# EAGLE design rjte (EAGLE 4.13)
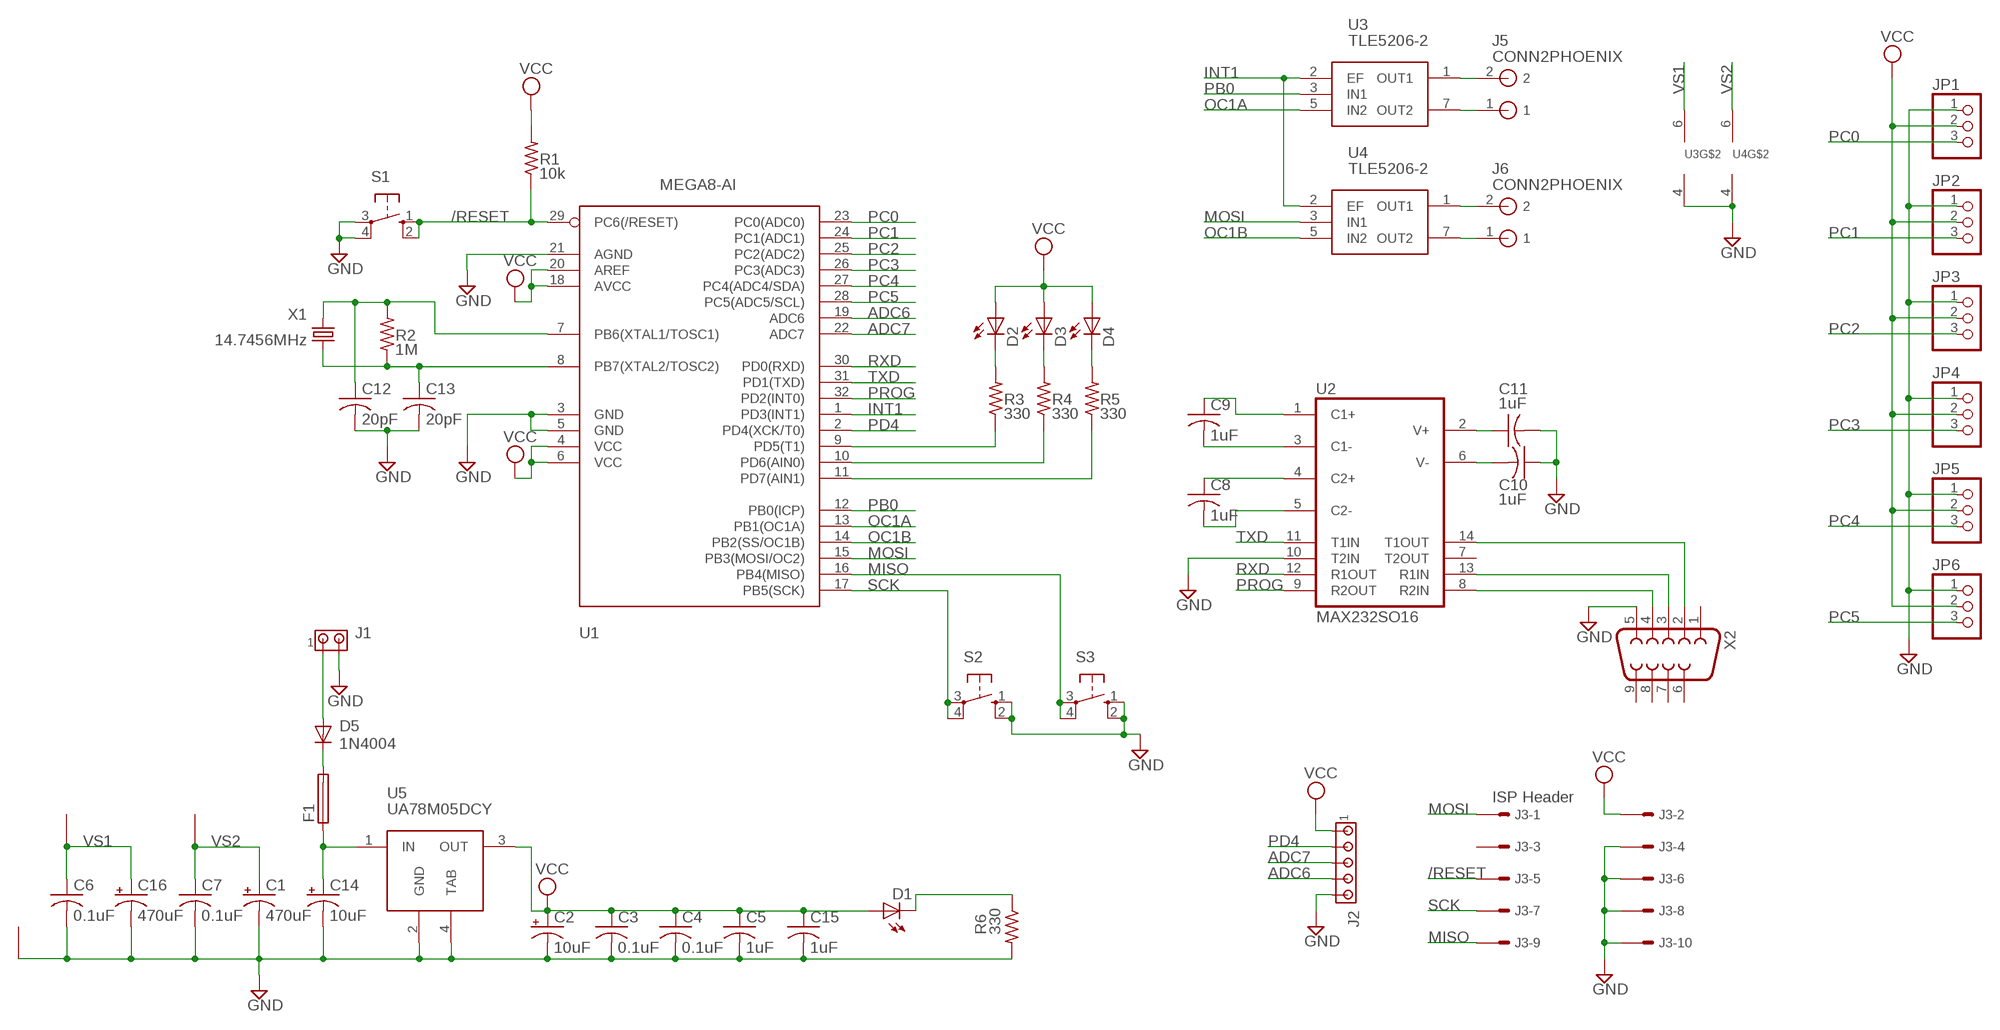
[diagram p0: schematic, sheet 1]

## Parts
C1  470uF  CPOL-USE5-10.5  [E5-10,5]
C2  10uF  CPOL-USB45181A  [B45181A]
C3  0.1uF  C-US025-030X050  [C025-030X050]
C4  0.1uF  C-US025-030X050  [C025-030X050]
C5  1uF  C-US025-025X050  [C025-025X050]
C6  0.1uF  C-US025-030X050  [C025-030X050]
C7  0.1uF  C-US025-030X050  [C025-030X050]
C8  1uF  C-US025-025X050  [C025-025X050]
C9  1uF  C-US025-025X050  [C025-025X050]
C10  1uF  C-US025-025X050  [C025-025X050]
C11  1uF  C-US025-025X050  [C025-025X050]
C12  20pF  C-US025-025X050  [C025-025X050]
C13  20pF  C-US025-025X050  [C025-025X050]
C14  10uF  CPOL-USB45181A  [B45181A]
C15  1uF  C-US025-025X050  [C025-025X050]
C16  470uF  CPOL-USE5-10.5  [E5-10,5]
D1  LED3MM  [LED3MM]
D2  LED3MM  [LED3MM]
D3  LED3MM  [LED3MM]
D4  LED3MM  [LED3MM]
D5  1N4004  [DO41-10]
F1  PICOFUSE  [PICOFUSE]
J1  MTA02-100  [10X02MTA]
J2  MTA05-100  [10X05MTA]
J3  ISP Header  057-010-1  [057-010-1]
J5  CONN2PHOENIX  [TB2]
J6  CONN2PHOENIX  [TB2]
JP1  PINHD-1X3  [1X03]
JP2  PINHD-1X3  [1X03]
JP3  PINHD-1X3  [1X03]
JP4  PINHD-1X3  [1X03]
JP5  PINHD-1X3  [1X03]
JP6  PINHD-1X3  [1X03]
R1  10k  R-US_0204/7  [0204/7]
R2  1M  R-US_0207/10  [0207/10]
R3  330  R-US_0207/10  [0207/10]
R4  330  R-US_0207/10  [0207/10]
R5  330  R-US_0207/10  [0207/10]
R6  330  R-US_0207/10  [0207/10]
S1  10-XX  [B3F-10XX]
S2  10-XX  [B3F-10XX]
S3  10-XX  [B3F-10XX]
U1  MEGA8-AI  [TQFP32-08]
U2  MAX232SO16  [SO16]
U3  TLE5206-2  TLE5206-2TLE5206-2  [TO220-7-11]
U4  TLE5206-2  TLE5206-2TLE5206-2  [TO220-7-11]
U5  UA78M05DCY  [SOT223]
U$1  12AWG_PAD  [12AWG_PAD]
U$3  12AWG_PAD  [12AWG_PAD]
U$4  12AWG_PAD  [12AWG_PAD]
X1  14.7456MHz  CRYTALHC49U-V  [HC49U-V]
X2  F09H  [F09H]

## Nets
/RESET: J3.5 R1.1 S1.1(S) S1.2(S1) U1.29(PC6(/RESET))
ADC6: J2.4 U1.19(ADC6)
ADC7: J2.3 U1.22(ADC7)
GND: C1.- C2.- C3.2 C4.2 C5.2 C6.2 C7.2 C10.1 C11.2 C12.2 C13.2 C14.- C15.2 C16.- J1.2 J2.5 J3.4 J3.6 J3.8 J3.10 JP1.1 JP2.1 JP3.1 JP4.1 JP5.1 JP6.1 R6.2 S1.3(P) S1.4(P1) S2.1(S) S2.2(S1) S3.1(S) S3.2(S1) U1.3(GND) U1.5(GND) U1.21(AGND) U2.10(T2IN) U3.4(GND) U4.4(GND) U5.2(GND) U5.4(TAB) U$4.P$1 X2.5
INT1: U1.1(PD3(INT1)) U3.2(EF) U4.2(EF)
MISO: J3.9 S3.3(P) S3.4(P1) U1.16(PB4(MISO))
MOSI: J3.1 U1.15(PB3(MOSI/OC2)) U4.3(IN1)
N$1: C13.1 R2.1 U1.8(PB7(XTAL2/TOSC2)) X1.1
N$2: C12.1 R2.2 U1.7(PB6(XTAL1/TOSC1)) X1.2
N$3: C8.1 U2.4(C2+)
N$4: C8.2 U2.5(C2-)
N$5: C9.2 U2.3(C1-)
N$6: C9.1 U2.1(C1+)
N$7: C10.2 U2.6(V-)
N$8: C11.1 U2.2(V+)
N$9: U2.14(T1OUT) X2.2
N$10: U2.13(R1IN) X2.3
N$11: U2.8(R2IN) X2.4
N$12: J5.2 U3.1(OUT1)
N$13: D2.K(C) R3.2
N$14: D3.K(C) R4.2
N$15: D4.K(C) R5.2
N$16: R5.1 U1.11(PD7(AIN1))
N$17: R4.1 U1.10(PD6(AIN0))
N$18: D1.K(C) R6.1
N$19: R3.1 U1.9(PD5(T1))
N$20: J5.1 U3.7(OUT2)
N$21: J6.2 U4.1(OUT1)
N$22: J6.1 U4.7(OUT2)
N$23: C14.+ F1.1 U5.1(IN)
N$24: D5.C F1.2
N$25: D5.A J1.1
OC1A: U1.13(PB1(OC1A)) U3.5(IN2)
OC1B: U1.14(PB2(SS/OC1B)) U4.5(IN2)
PB0: U1.12(PB0(ICP)) U3.3(IN1)
PC0: JP1.3 U1.23(PC0(ADC0))
PC1: JP2.3 U1.24(PC1(ADC1))
PC2: JP3.3 U1.25(PC2(ADC2))
PC3: JP4.3 U1.26(PC3(ADC3))
PC4: JP5.3 U1.27(PC4(ADC4/SDA))
PC5: JP6.3 U1.28(PC5(ADC5/SCL))
PD4: J2.2 U1.2(PD4(XCK/T0))
PROG: U1.32(PD2(INT0)) U2.9(R2OUT)
RXD: U1.30(PD0(RXD)) U2.12(R1OUT)
SCK: J3.7 S2.3(P) S2.4(P1) U1.17(PB5(SCK))
TXD: U1.31(PD1(TXD)) U2.11(T1IN)
VCC: C2.+ C3.1 C4.1 C5.1 C15.1 D1.A D2.A D3.A D4.A J2.1 J3.2 JP1.2 JP2.2 JP3.2 JP4.2 JP5.2 JP6.2 R1.2 U1.4(VCC) U1.6(VCC) U1.18(AVCC) U1.20(AREF) U5.3(OUT)
VS1: C6.1 C16.+ U3.6(VS) U$1.P$1
VS2: C1.+ C7.1 U4.6(VS) U$3.P$1
Unconnected: J3.3 U2.7(T2OUT) X2.1 X2.6 X2.7 X2.8 X2.9

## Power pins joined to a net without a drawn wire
GND: U2.15(GND)
VCC: U2.16(VCC)

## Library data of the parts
C1 C2 C14 C16 = rcl:CPOL-US: POLARIZED CAPACITOR, American symbol
C3-C13 C15 = rcl:C-US: CAPACITOR, American symbol
D1-D4 = led:LED: LED
D5 = diode:1N4004: DIODE
F1 = fuse:PICOFUSE: PICOFUSE
J1 = con-amp:MTA02-100: AMP connector
J2 = con-amp:MTA05-100: AMP connector
J3 = con-panduit:057-010-: CONNECTOR 10-pin series 057 contact pc board low profile headers
J5 J6 = rjte:CONN2
JP1-JP6 = rjte:PINHD-1X3: PIN HEADER
R1-R6 = rcl:R-US_: RESISTOR, American symbol
S1-S3 = switch-omron:10-XX: OMRON SWITCH
U1 = atmel:MEGA8: MICROCONTROLLER 8 Kbytes FLASH 1 kbytes SRAM 512 bytes EEPROM USART 6-channel 10 bit ADC 2-channel 8 bit ADC
U2 = rjte:MAX232: RS232 TRANSEIVER
U3 U4 = rjte:TLE5206-2
U5 = rjte:UA78M05
U$1 U$3 U$4 = rjte:12AWG_PAD
X1 = crystal:CRYTAL: CRYSTAL
X2 = rjte:F09: SUB-D

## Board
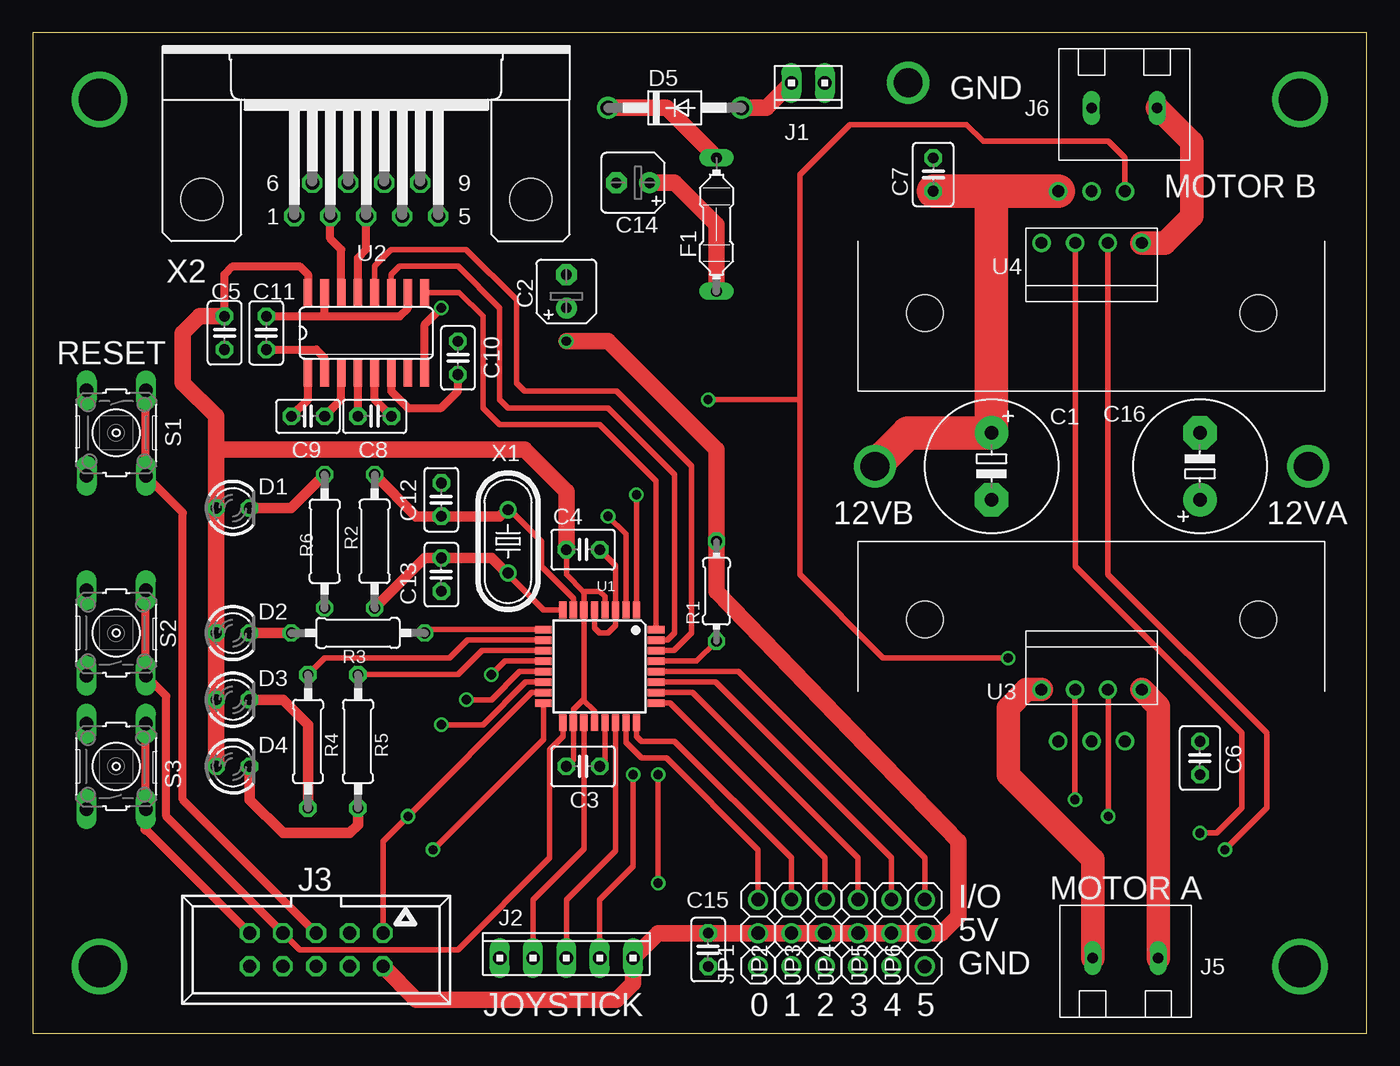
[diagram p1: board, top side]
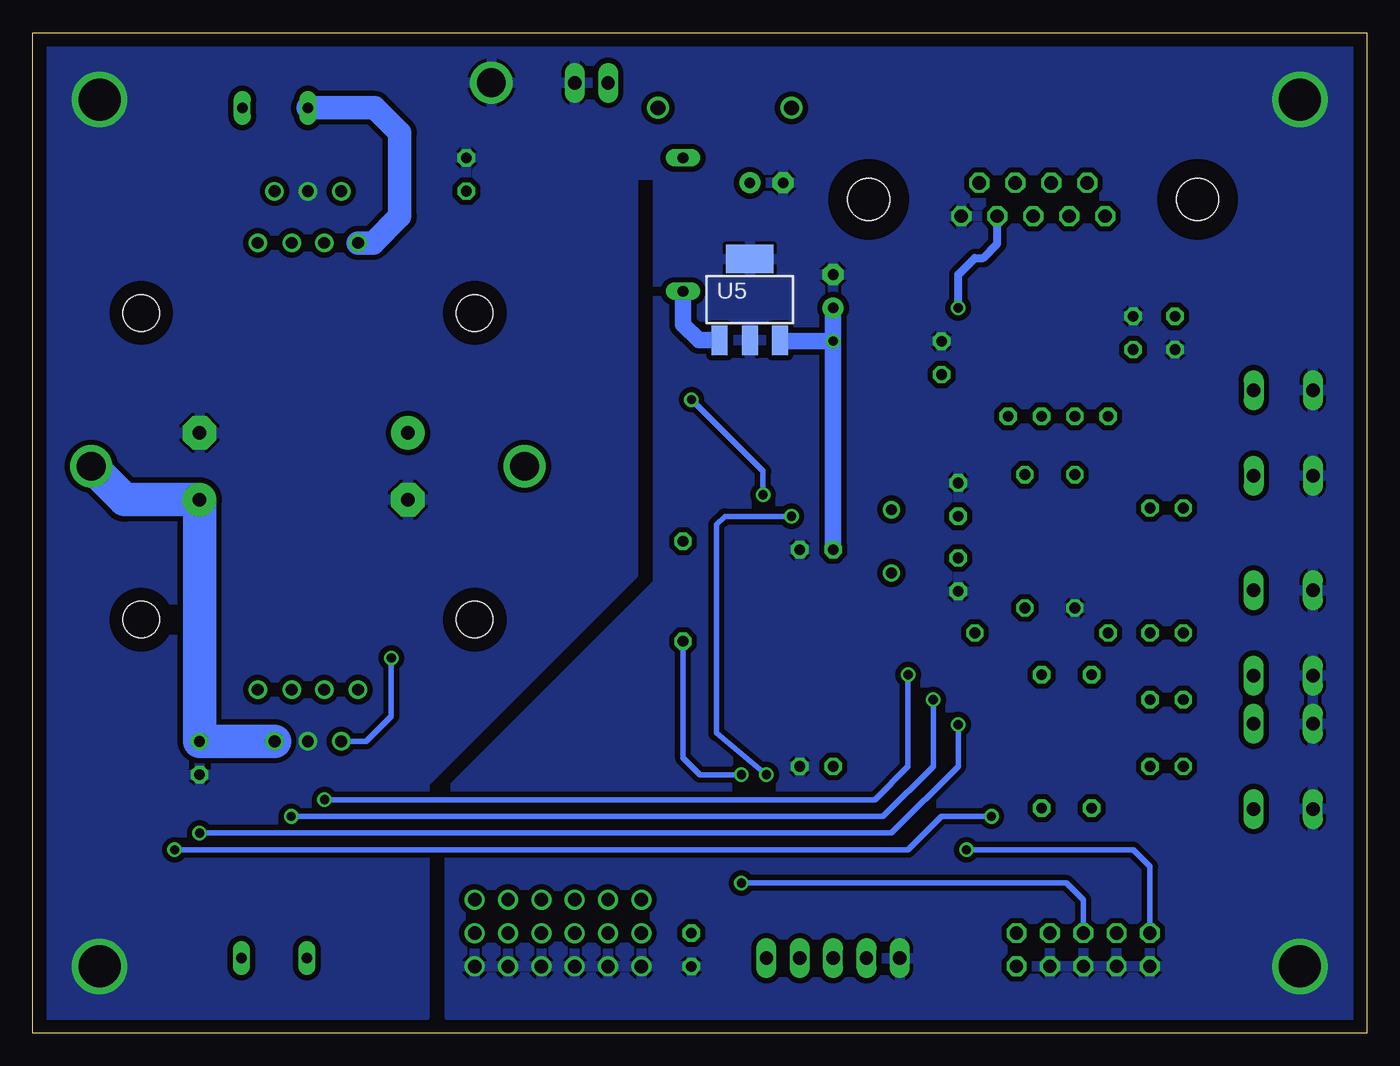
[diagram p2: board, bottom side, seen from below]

Size 101.6 x 76.2 mm. Coordinates in mm from the lower left corner, seen from the top.
Outline: 0,0 101.6,0 101.6,76.2 0,76.2 0,0
Copper layers (1*16): Top 0.035mm / dielectric 1.5mm / Bottom 0.035mm
Design rules "default": minimum track width 10mil, minimum drill 24mil, track to track 8mil, track to pad 8mil, pad to pad 8mil, via to via 8mil, smd to smd 8mil, copper to edge 40mil, drill to drill 8mil, minimum pad ring 10mil, minimum via ring 8mil, stop-mask expansion 4mil, vias tented up to drill 0mil, thermal gap 10mil
tKeepout: area 1.3,67.3 to 8.9,74.9; area 1.3,1.3 to 8.9,8.9; area 92.7,1.3 to 100.3,8.9; area 92.7,67.3 to 100.3,74.9

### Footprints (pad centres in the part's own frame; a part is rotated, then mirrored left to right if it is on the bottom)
E5-10,5 = drill 1.016 pad 2.54 round: + -2.54,0 | drill 1.016 pad 2.54 octagon: - 2.54,0
B45181A = drill 0.813 pad 1.6 round: + -1.27,0 | drill 0.813 pad 1.6 octagon: - 1.27,0
C025-030X050 = drill 0.813 octagon: 1 -1.27,0; 2 1.27,0
C025-025X050 = drill 0.813 octagon: 1 -1.27,0; 2 1.27,0
LED3MM = drill 0.813 octagon: A -1.27,0; K 1.27,0
DO41-10 = drill 1.118 round: A 5.08,0; C -5.08,0
PICOFUSE = drill 0.813 long: 1 -5.08,0; 2 5.08,0
10X02MTA = drill 1.016 long: 1 1.27,0; 2 -1.27,0
10X05MTA = drill 1.016 long: 1 5.08,0; 2 2.54,0; 3 0,0; 4 -2.54,0; 5 -5.08,0
057-010-1 = drill 1 octagon: 1 -5.08,-1.27; 2 -5.08,1.27; 3 -2.54,-1.27; 4 -2.54,1.27; 5 0,-1.27; 6 0,1.27; 7 2.54,-1.27; 8 2.54,1.27; 9 5.08,-1.27; 10 5.08,1.27
TB2 = drill 0.8 long: 1 0,0; 2 5,0
1X03 = drill 1.016 round: 1 -2.54,0; 2 0,0; 3 2.54,0
0204/7 = drill 0.813 octagon: 1 -3.81,0; 2 3.81,0
0207/10 = drill 0.813 octagon: 1 -5.08,0; 2 5.08,0
B3F-10XX = drill 1.016 long: 1 -3.251,2.261; 2 3.251,2.261; 3 -3.251,-2.261; 4 3.251,-2.261
TQFP32-08@1 = smd 1.27 x 0.559: 1 -4.293,2.8; 2 -4.293,2; 3 -4.293,1.2; 4 -4.293,0.4; 5 -4.293,-0.4; 6 -4.293,-1.2; 7 -4.293,-2; 8 -4.293,-2.8; 17 4.293,-2.8; 18 4.293,-2; 19 4.293,-1.2; 20 4.293,-0.4; 21 4.293,0.4; 22 4.293,1.2; 23 4.293,2; 24 4.293,2.8 | smd 0.559 x 1.27: 9 -2.8,-4.293; 10 -2,-4.293; 11 -1.2,-4.293; 12 -0.4,-4.293; 13 0.4,-4.293; 14 1.2,-4.293; 15 2,-4.293; 16 2.8,-4.293; 25 2.8,4.293; 26 2,4.293; 27 1.2,4.293; 28 0.4,4.293; 29 -0.4,4.293; 30 -1.2,4.293; 31 -2,4.293; 32 -2.8,4.293
SO16 = smd 0.66 x 2.032: 1 -4.445,-3.073; 2 -3.175,-3.073; 3 -1.905,-3.073; 4 -0.635,-3.073; 5 0.635,-3.073; 6 1.905,-3.073; 7 3.175,-3.073; 8 4.445,-3.073; 9 4.445,3.073; 10 3.175,3.073; 11 1.905,3.073; 12 0.635,3.073; 13 -0.635,3.073; 14 -1.905,3.073; 15 -3.175,3.073; 16 -4.445,3.073
TO220-7-11 = drill 0.9 round: 1 -3.82,3.94; 2 -2.54,0; 3 -1.24,3.94; 4 0,0; 5 1.24,3.94; 6 2.54,0; 7 3.82,3.94 | hole 2.8: -12.7,9.271; 12.7,9.271
SOT223 = smd 1.219 x 2.235: 1 -2.311,-3.099; 2 0,-3.099; 3 2.311,-3.099 | smd 3.6 x 2.2: 4 0,3.099
12AWG_PAD = drill 2.2 round: P$1 0,0
HC49U-V = drill 0.813 round: 1 -2.413,0; 2 2.413,0
F09H = drill 1.016 octagon: 1 -5.486,-1.27; 2 -2.743,-1.27; 3 0,-1.27; 4 2.743,-1.27; 5 5.486,-1.27; 6 -4.115,1.27; 7 -1.372,1.27; 8 1.372,1.27; 9 4.115,1.27 | hole 3.2: -12.522,0; 12.522,0

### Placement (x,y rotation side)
C1  73.03,43.18 270 top
C2  40.64,56.52 90 top
C3  41.91,20.32 0 top
C4  41.91,36.83 0 top
C5  14.61,53.34 270 top
C6  88.9,20.95 270 top
C7  68.58,65.41 90 top
C8  26.04,46.99 0 top
C9  20.95,46.99 0 top
C10  32.38,51.44 270 top
C11  17.78,53.34 90 top
C12  31.11,40.64 90 top
C13  31.11,34.92 270 top
C14  45.72,64.77 180 top
C15  51.44,6.35 270 top
C16  88.9,43.18 90 top
D1  15.24,40.01 0 top
D2  15.24,30.48 0 top
D3  15.24,25.4 0 top
D4  15.24,20.32 0 top
D5  48.9,70.48 0 top
F1  52.07,61.59 90 top
J1  59.05,72.39 180 top
J2  40.64,5.71 0 top
J3  21.59,6.35 180 top
J5  85.72,5.71 180 top
J6  80.64,70.48 0 top
JP1  55.24,7.62 90 top
JP2  57.78,7.62 90 top
JP3  60.33,7.62 90 top
JP4  62.87,7.62 90 top
JP5  65.41,7.62 90 top
JP6  67.94,7.62 90 top
R1  52.07,33.66 90 top
R2  26.04,37.47 90 top
R3  24.77,30.48 180 top
R4  20.95,22.23 270 top
R5  24.77,22.23 270 top
R6  22.23,37.47 270 top
S1  6.35,45.72 270 top
S2  6.35,30.48 90 top
S3  6.35,20.32 90 top
U1  MEGA8-AI  [TQFP32-08@1]  43.18,27.94 270 top
U2  25.4,53.34 0 top
U3  80.64,22.23 0 top
U4  80.64,64.14 180 top
U5  46.99,55.88 0 bottom
U$1  97.16,43.18 0 top
U$3  64.14,43.18 0 top
U$4  66.67,72.39 0 top
X1  36.2,37.47 90 top
X2  25.4,63.5 0 top

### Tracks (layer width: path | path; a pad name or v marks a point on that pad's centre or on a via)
/RESET  (via drill 0.7)
  Top 0.406: U1.29 50.56,28.34 R1.1 | v47.62,11.43 v47.62,19.68
  Top 0.61: J3.5 11.43,17.78 11.43,39.65 S1.2 8.61,48.54 | 8.33,48.97 S1.1
  Top 0.813: 8.33,48.97 8.26,48.9 8.61,48.54
  Bottom 0.406: v47.62,19.68 50.8,19.68 52.07,20.95 R1.1 | v47.62,11.43 22.86,11.43 21.59,10.16 J3.5
ADC6
  Top 0.406: U1.19 41.98,14.04 38.1,10.16 J2.4
ADC7
  Top 0.406: U1.22 44.38,13.9 40.64,10.16 J2.3
GND  (via drill 3.2)
  Top 0.406: U1.21 43.58,20.72 C3.2 | U1.5 42.78,30.88 43.18,30.48 43.81,30.48 44.38,31.05 U1.3 44.38,35.63 C4.2
  Top 0.61: 22.23,54.61 U2.15 | C11.2 22.23,54.61 | U2.10 28.57,55.24 27.94,54.61 22.23,54.61
  other vias: 5.08,71.12 96.52,71.12 96.52,5.08 5.08,5.08
  pour Bottom (isolate 0.406): 1.27,1.27 69.85,1.27 69.85,18.41 53.98,34.29 53.98,65.41 55.88,65.41 55.88,34.92 71.75,19.05 71.75,1.27 100.33,1.27 100.33,74.93 1.27,74.93
INT1  (via drill 0.7)
  Top 0.406: U1.1 v45.98,41.02 | U4.2 83.19,66.67 81.92,67.94 72.39,67.94 71.12,69.22 62.23,69.22 58.42,65.41 58.42,48.26 | v51.44,48.26 58.42,48.26 | 58.42,48.26 58.42,34.92 64.77,28.57 v74.3,28.57
  Bottom 0.406: U3.2 76.2,22.23 74.3,24.13 v74.3,28.57 | v45.98,41.02 45.98,42.8 v51.44,48.26
MISO  (via drill 0.7)
  Top 0.406: U1.16 38.89,22.38 v30.48,13.97
  Top 0.61: J3.9 8.61,15.52 | 8.81,23.57 S3.4 | S3.3 8.61,23.22
  Top 0.813: 8.61,15.52 S3.3 | 8.81,23.57 8.89,23.5 8.61,23.22
  Bottom 0.406: v30.48,13.97 17.78,13.97 16.51,12.7 J3.9
MOSI  (via drill 0.7)
  Top 0.406: U1.15 38.01,25.94 v28.57,16.51 26.67,14.61 J3.1 | U4.3 81.89,34.95 93.98,22.86 93.98,17.14 v90.81,13.97
  Bottom 0.406: v90.81,13.97 34.92,13.97 32.38,16.51 v28.57,16.51
N$1
  Top 0.406: X1.1 36.2,34.92 38.89,32.23 U1.8
  Top 0.813: 36.2,34.92 34.92,36.2 C13.1 29.84,36.2 R2.1
N$2
  Top 0.406: U1.7 41.18,33.12 38.73,35.56 38.73,37.47 36.2,40.01 X1.2
  Top 0.813: 36.2,40.01 35.56,39.37 C12.1 29.21,39.37 R2.2
N$3
  Top 0.61: C8.1 U2.4
N$4
  Top 0.61: U2.5 26.04,48.26 C8.2
N$5
  Top 0.61: U2.3 23.5,48.26 C9.2
N$6
  Top 0.61: U2.1 20.95,48.26 C9.1
N$7
  Top 0.61: U2.6 27.3,48.9 28.57,47.62 31.11,47.62 32.38,48.9 C10.2
N$8
  Top 0.61: U2.2 22.23,51.44 21.59,52.07 C11.1
N$9
  Top 0.61: U2.14 23.5,59.69 22.66,60.53 X2.2
N$10
  Top 0.61: U2.13 24.77,59.05 25.4,59.69 X2.3
N$11  (via drill 0.7)
  Top 0.61: U2.8 29.84,53.98 v31.11,55.24
  Bottom 0.61: v31.11,55.24 31.11,57.78 29.84,59.05 29.21,59.05 28.14,60.12 X2.4
N$12
  Top 1.778: U3.1 75.69,26.16 74.3,24.77 74.3,19.68 80.72,13.26 J5.2
N$13
  Top 0.813: D2.K R3.2
N$14
  Top 0.813: D3.K 19.05,25.4 20.95,23.5 R4.2
N$15
  Top 0.813: D4.K 16.51,17.78 19.05,15.24 24.13,15.24 24.77,15.88 R5.2
N$16
  Top 0.406: U1.11 34.22,29.14 32.38,27.3 R5.1
N$17
  Top 0.406: U1.10 33.12,29.94 31.75,28.57 22.23,28.57 R4.1
N$18
  Top 0.813: D1.K 19.68,40.01 R6.1
N$19
  Top 0.406: 30.11,30.74 U1.9
  Top 0.61: R3.1 30.11,30.74
N$20
  Top 1.778: U3.7 85.72,24.91 J5.1
N$21
  Top 1.778: U4.1 86.23,60.2 88.27,62.23 88.27,67.86 J6.2
N$22
  Bottom 1.778: U4.7 75.69,60.2 73.66,62.23 73.66,68.58 75.56,70.48 J6.1
N$23
  Top 1.27: F1.1 52.07,61.59 48.9,64.77 C14.+
  Bottom 1.27: U5.1 50.88,52.78 52.07,53.98 F1.1
N$24
  Top 1.27: D5.C 48.26,70.48 F1.2
N$25
  Top 1.27: D5.A 55.88,70.48 J1.1
OC1A  (via drill 0.7)
  Top 0.406: U1.13 37.06,27.54 34.92,25.4 v33.02,25.4 | U3.5 81.89,26.07 81.92,26.04 v81.92,16.51
  Bottom 0.406: v33.02,25.4 33.02,20.32 36.83,16.51 v81.92,16.51
OC1B  (via drill 0.7)
  Top 0.406: U1.14 37.53,26.74 34.29,23.5 v31.11,23.5 | v88.9,15.24 90.17,15.24 92.08,17.14 92.08,22.86 79.41,35.53 U4.5
  Bottom 0.406: v31.11,23.5 31.11,20.32 36.2,15.24 v88.9,15.24
PB0  (via drill 0.7)
  Top 0.406: U1.12 35.96,28.34 v34.92,27.3 | U3.3 79.41,26.07 79.38,26.04 v79.38,17.78
  Bottom 0.406: v34.92,27.3 34.92,20.32 37.47,17.78 v79.38,17.78
PC0
  Top 0.406: U1.23 45.18,22.13 46.35,20.95 48.26,20.95 55.24,13.97 JP1.3
PC1
  Top 0.406: U1.24 45.98,22.6 46.35,22.23 48.9,22.23 57.78,13.34 JP2.3
PC2
  Top 0.406: JP3.3 60.33,13.34 48.52,25.14 U1.25
PC3
  Top 0.406: U1.26 50.26,25.94 62.87,13.34 JP4.3
PC4
  Top 0.406: U1.27 52,26.74 65.41,13.34 JP5.3
PC5
  Top 0.406: U1.28 53.74,27.54 67.94,13.34 JP6.3
PD4  (via drill 0.7)
  Top 0.406: U1.2 45.18,38.01 v43.81,39.37 | v45.72,19.68 45.72,12.7 43.18,10.16 J2.2
  Bottom 0.406: v45.72,19.68 49.53,22.86 49.53,38.73 48.9,39.37 v43.81,39.37
PROG
  Top 0.406: U2.9 32.49,56.41 34.29,54.61 34.29,47.62 35.56,46.35 43.18,46.35 47.47,42.06 U1.32
RXD
  Top 0.406: U2.12 26.04,58.42 27.3,59.69 33.02,59.69 36.83,55.88 36.83,49.53 37.47,48.9 44.45,48.9 50.16,43.18 50.16,30.48 48.83,29.14 U1.30
SCK
  Top 0.406: U1.17 40.38,22.6 39.37,21.59 39.37,13.34 32.38,6.35 20.32,6.35 J3.7
  Top 0.61: J3.7 10.16,16.51 10.16,25.68 S2.3 8.61,33.38 8.89,33.66 | 8.81,33.73 S2.4
  Top 0.813: 8.89,33.66 8.81,33.73
TXD
  Top 0.406: U1.31 48.35,29.94 48.9,30.48 48.9,42.55 43.81,47.62 36.2,47.62 35.56,48.26 35.56,55.24 32.38,58.42 27.94,58.42 27.3,57.78 U2.11
VCC  (via drill 0.7)
  Top 0.406: C3.1 41.18,20.86 U1.18 41.18,24.67 41.91,25.4 | U1.20 42.78,24.53 41.91,25.4 | 41.91,25.4 41.98,25.47 U1.6 41.98,33.59 41.91,33.66 | U1.4 43.58,33.26 43.18,33.66 41.91,33.66 | 41.91,33.66 40.64,34.92 C4.1
  Top 0.61: U2.16 20.95,57.78 20.32,58.42 15.24,58.42 14.61,57.78 C5.1
  Top 1.27: D4.A D3.A D2.A D1.A 13.97,44.45 | 13.97,44.45 13.97,46.99 11.43,49.53 11.43,53.34 12.7,54.61 C5.1 | 13.97,44.45 37.47,44.45 40.64,41.27 C4.1 | JP1.2 C15.1 47.62,7.62 J2.1 45.72,3.81 44.45,2.54 29.21,2.54 J3.2 | JP1.2 JP2.2 | JP1.2 JP3.2 JP4.2 JP5.2 JP6.2 69.22,7.62 70.48,8.89 70.48,14.61 52.07,33.66 R1.2 52.07,44.45 43.81,52.7 v40.64,52.7
  Bottom 1.27: v40.64,52.7 C4.1 | v40.64,52.7 C2.+ | U5.3 44.6,52.7 v40.64,52.7
VS1
  Bottom 2.54: U3.6 C6.1 C16.+ 94.61,40.64 U$1.P$1
VS2
  Top 2.54: U4.6 C7.1 73.03,64.14 C1.+ 66.67,45.72 U$3.P$1

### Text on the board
tPlace: GND | MOTOR B | 12VB | 12VA | I/O | MOTOR A | 5V | GND | JOYSTICK | 0 | 1 | 2 | 3 | 4 | 5
tNames: RESET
